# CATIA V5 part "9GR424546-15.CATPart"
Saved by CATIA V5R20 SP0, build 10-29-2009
Part number: 9GR424546-15
Revision: ANY
Definition: UNKNOWN
Nomenclature: 9GR424546-15
Source: Unknown
Bounding box of the stored display mesh (mm): x -22.944 to 23, y -40 to 5, z -23 to 23
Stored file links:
  C:\Users\Utente\Desktop\IO LAVORO\3D X SITO CF\CUMSA\3D files GR\GR 424546-15\9GR424546-15.CATPart
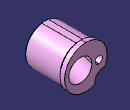
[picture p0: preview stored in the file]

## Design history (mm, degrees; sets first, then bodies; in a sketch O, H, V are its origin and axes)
Body1 "Cortar-Extruir7" (main body)
  Solid1: solid without history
